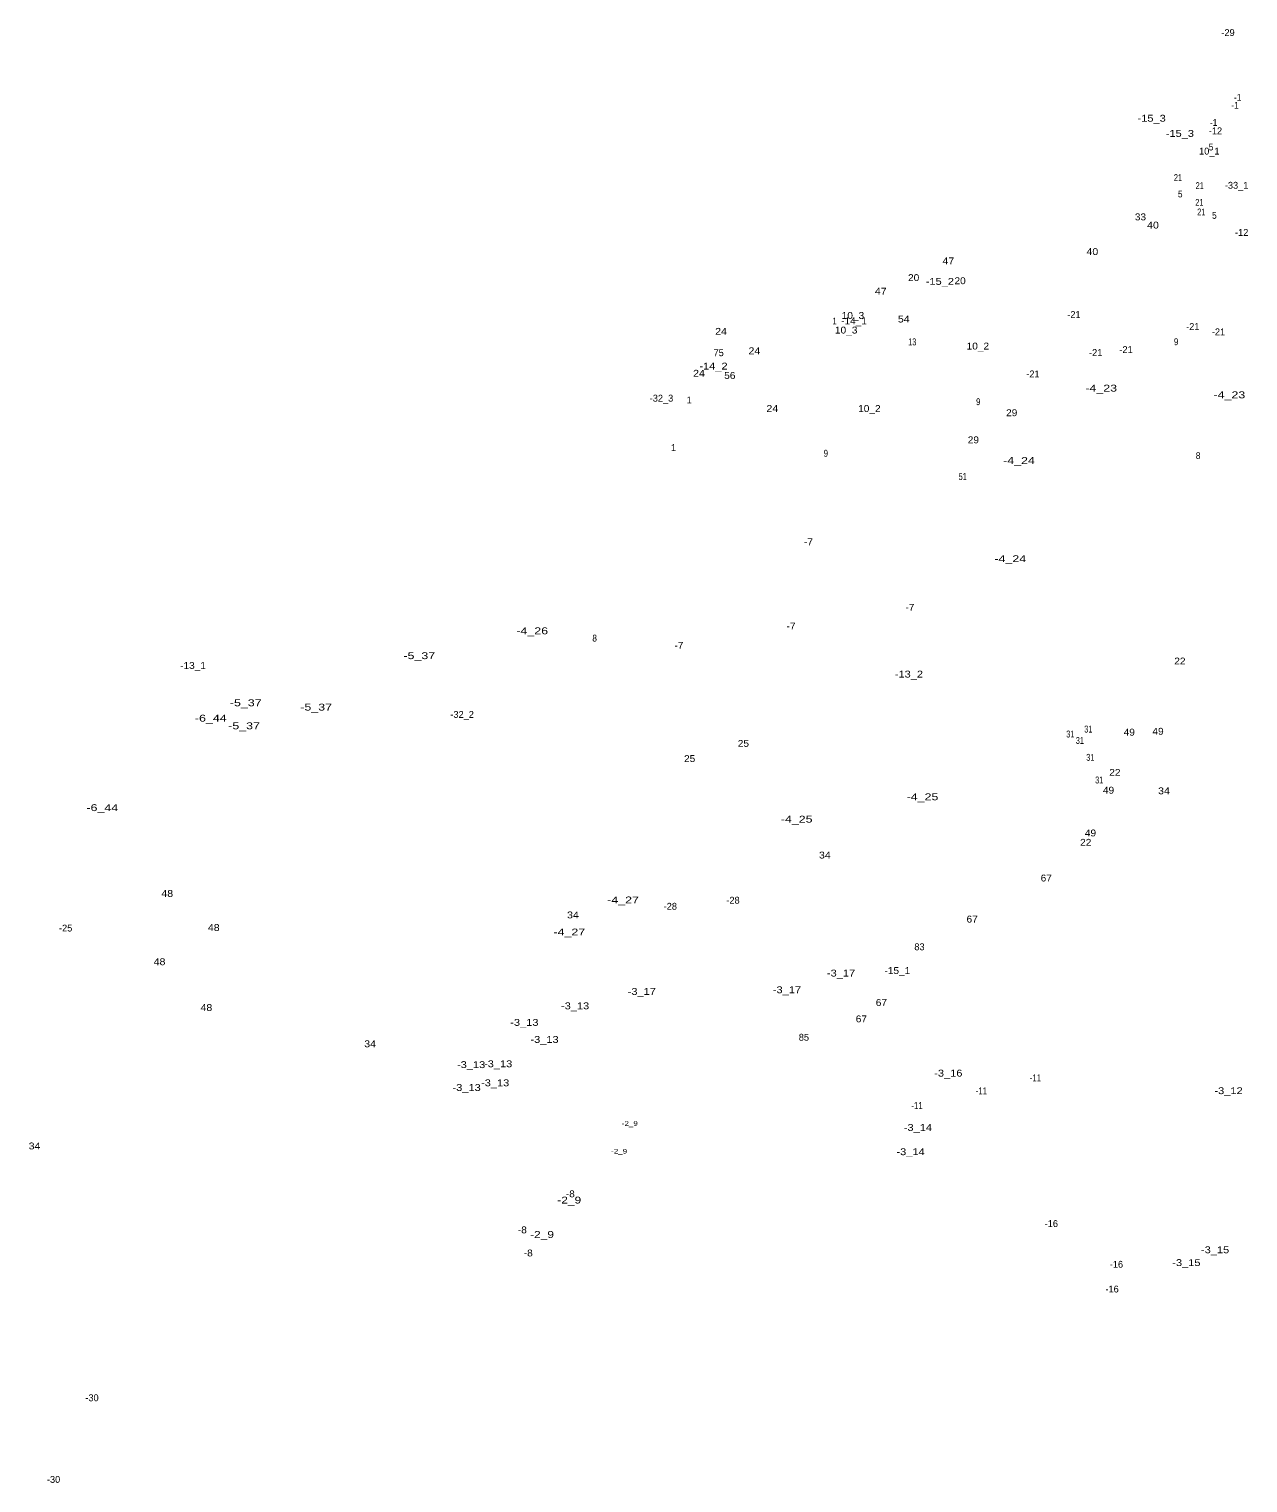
# Model space of a CAD drawing. Extents: x -660778 to -658007, y -986975 to -985382.
# Drawn here: x -659382 to -658674, y -986509 to -985663 of the extents above; entities that cross this region are included whole.
import ezdxf
from ezdxf.enums import TextEntityAlignment as Align

# ---------------------------------------------------------------- set-up
doc = ezdxf.new("R2010")
doc.units = 0
doc.header["$LTSCALE"] = 1.6
doc.layers.add('24', color=7, linetype='Continuous')

msp = doc.modelspace()

# ---------------------------------------------------------------- texts
at = {"layer": '24'}
for s, p in [('-29', (-658685.15, -985667.27)), ('-12', (-658692.441, -985724.41)), ('10_1', (-658696.03, -985736.19)), ('-33_1', (-658680.156, -985756.05)), ('-12', (-658677.201, -985783.44)), ('-21', (-658774.74, -985831.18)), ('-21', (-658705.64, -985838.17)), ('-21', (-658690.691, -985841.28)), ('-21', (-658744.461, -985851.57)), ('75', (-658981.363, -985853.42)), ('-21', (-658762.12, -985853.32)), ('-21', (-658798.611, -985865.75)), ('-32_3', (-659014.612, -985879.85)), ('1', (-658998.502, -985880.88)), ('1', (-659007.632, -985908.58)), ('-32_2', (-659130.542, -986063.75)), ('-28', (-658973.025, -986171.8)), ('-28', (-659009.475, -986175.32)), ('-25', (-659361.095, -986187.97)), ('83', (-658864.597, -986198.87)), ('85', (-658931.787, -986251.48)), ('-16', (-658787.9, -986359.83)), ('-16', (-658750.05, -986383.51)), ('-16', (-658752.57, -986397.88)), ('-30', (-659345.769, -986461.11)), ('-30', (-659368.119, -986508.57))]:
    msp.add_text(s, height=4, dxfattribs=at).set_placement(p, align=Align.CENTER)
for s, height, width, p in [('-1', 4, 0.9, (-658679.51, -985704.91)), ('-15_3', 4, 1.2, (-658729.549, -985717.07)), ('-1', 4, 0.9, (-658681.061, -985709.52)), ('-1', 4, 0.9, (-658693.53, -985719.52)), ('-15_3', 4, 1.2, (-658713.15, -985725.9)), ('5', 4, 0.9, (-658695, -985733.78)), ('21', 4, 0.8, (-658714.25, -985751.56)), ('21', 4, 0.8, (-658701.62, -985756.27)), ('5', 4, 0.9, (-658712.939, -985761.09)), ('21', 4, 0.8, (-658701.809, -985765.98)), ('33', 4, 1.1, (-658736.079, -985774.43)), ('21', 4, 0.8, (-658700.699, -985771.56)), ('5', 4, 0.9, (-658693.09, -985773.53)), ('40', 4, 1.15, (-658728.78, -985779.2)), ('47', 4, 1.15, (-658847.8, -985800.02)), ('40', 4, 1.15, (-658764.04, -985794.61)), ('20', 4, 1.1, (-658867.97, -985809.73)), ('47', 4, 1.15, (-658887.11, -985817.64)), ('-15_2', 4, 1.2, (-658852.73, -985811.93)), ('20', 4, 1.1, (-658840.959, -985811.56)), ('1', 4, 0.65, (-658913.927, -985834.98)), ('-14_1', 4, 1.1, (-658902.65, -985834.92)), ('10_3', 4, 1.1, (-658903.27, -985831.75)), ('54', 4, 1.15, (-658873.72, -985833.82)), ('24', 4, 1.15, (-658979.959, -985840.99)), ('10_3', 4, 1.1, (-658907.2, -985840.24)), ('24', 4, 1.15, (-658960.579, -985852.33)), ('13', 4, 0.8, (-658868.79, -985847.11)), ('10_2', 4, 1.1, (-658830.63, -985849.54)), ('9', 4, 0.85, (-658715.31, -985847.03)), ('24', 4, 1.15, (-658992.79, -985865.37)), ('-14_2', 4, 1.2, (-658984.36, -985861.17)), ('56', 4, 1.1, (-658974.86, -985866.64)), ('-4_23', 4, 1.35, (-658758.9, -985874.01)), ('-4_23', 4, 1.35, (-658684.36, -985877.89)), ('24', 4, 1.15, (-658950.169, -985885.85)), ('10_2', 4, 1.1, (-658893.71, -985885.85)), ('9', 4, 0.85, (-658830.4, -985881.88)), ('29', 4, 1.1, (-658810.94, -985888.31)), ('29', 4, 1.1, (-658833.24, -985904.08)), ('9', 4, 0.85, (-658919.02, -985911.88)), ('-4_24', 4, 1.35, (-658806.72, -985916.1)), ('8', 4, 0.9, (-658702.569, -985913.26)), ('51', 4, 0.8, (-658839.439, -985925.4)), ('-7', 4, 1.1, (-658929.15, -985963.39)), ('-4_24', 4, 1.35, (-658811.77, -985973.18)), ('-7', 4, 1.1, (-658870.15, -986001.45)), ('-7', 4, 1.1, (-658939.25, -986012.32)), ('-4_26', 4, 1.35, (-659089.78, -986015.13)), ('8', 4, 0.9, (-659053.48, -986019.37)), ('-5_37', 4, 1.35, (-659155.44, -986029.59)), ('-7', 4, 1.1, (-659004.471, -986023.58)), ('-13_1', 4, 1.1, (-659287.01, -986035.28)), ('22', 4, 1.1, (-658713.13, -986032.69)), ('-13_2', 4, 1.2, (-658870.73, -986040.3)), ('-5_37', 4, 1.35, (-659256.38, -986056.97)), ('-5_37', 4, 1.35, (-659215.42, -986059.5)), ('-6_44', 4, 1.35, (-659276.699, -986065.92)), ('-5_37', 4, 1.35, (-659257.35, -986070.37)), ('31', 4, 0.8, (-658766.4, -986072.26)), ('25', 4, 1.1, (-658966.98, -986080.58)), ('31', 4, 0.8, (-658776.87, -986075.14)), ('31', 4, 0.8, (-658771.299, -986078.89)), ('49', 4, 1.1, (-658742.58, -986074.08)), ('49', 4, 1.1, (-658725.85, -986073.55)), ('31', 4, 0.8, (-658765.24, -986088.7)), ('25', 4, 1.1, (-658998.22, -986089.42)), ('22', 4, 1.1, (-658750.949, -986097.44)), ('31', 4, 0.8, (-658760.049, -986101.87)), ('-4_25', 4, 1.35, (-658862.82, -986111.65)), ('49', 4, 1.1, (-658754.65, -986107.81)), ('34', 4, 1.15, (-658722.39, -986108.18)), ('-6_44', 4, 1.35, (-659339.78, -986117.96)), ('-4_25', 4, 1.35, (-658936, -986124.66)), ('22', 4, 1.1, (-658767.88, -986138.12)), ('49', 4, 1.1, (-658765.15, -986132.67)), ('34', 4, 1.15, (-658919.6, -986145.53)), ('67', 4, 1.1, (-658790.84, -986158.88)), ('48', 4, 1.15, (-659302.02, -986167.84)), ('-4_27', 4, 1.35, (-659036.939, -986171.63)), ('34', 4, 1.15, (-659066.1, -986180.35)), ('48', 4, 1.15, (-659274.98, -986187.7)), ('-4_27', 4, 1.35, (-659068.189, -986190.27)), ('67', 4, 1.1, (-658833.93, -986182.77)), ('48', 4, 1.15, (-659306.5, -986207.55)), ('-3_17', 4, 1.2, (-658910.19, -986214.16)), ('-15_1', 4, 1.1, (-658877.449, -986212.67)), ('-3_17', 4, 1.2, (-658941.64, -986223.86)), ('-3_17', 4, 1.2, (-659026.07, -986224.83)), ('67', 4, 1.1, (-658886.72, -986231.27)), ('48', 4, 1.15, (-659279.26, -986234.22)), ('-3_13', 4, 1.2, (-659064.84, -986233.21)), ('67', 4, 1.1, (-658898.37, -986240.79)), ('-3_13', 4, 1.2, (-659094.34, -986242.83)), ('34', 4, 1.15, (-659184.04, -986255.29)), ('-3_13', 4, 1.2, (-659082.6, -986252.73)), ('-3_13', 4, 1.2, (-659125.299, -986267.39)), ('-3_13', 4, 1.2, (-659109.579, -986266.9)), ('-3_16', 4, 1.2, (-658847.791, -986272.34)), ('-11', 4, 0.85, (-658797.13, -986275.06)), ('-3_13', 4, 1.2, (-659127.919, -986280.69)), ('-3_13', 4, 1.2, (-659111.319, -986277.97)), ('-11', 4, 0.85, (-658828.571, -986282.63)), ('-3_12', 4, 1.2, (-658684.84, -986282.55)), ('-11', 4, 0.85, (-658866.03, -986291.17)), ('-2_9', 2.68, 1.3, (-659033.02, -986300.99)), ('-3_14', 4, 1.2, (-658865.48, -986303.95)), ('34', 4, 1.15, (-659379.179, -986314.69)), ('-2_9', 2.68, 1.3, (-659039.23, -986317.1)), ('-3_14', 4, 1.2, (-658869.75, -986318.03)), ('-8', 4, 1.1, (-659067.62, -986342.52)), ('-2_9', 4, 1.3, (-659068.25, -986346.16)), ('-8', 4, 1.1, (-659095.52, -986363.49)), ('-2_9', 4, 1.3, (-659084.07, -986366.16)), ('-3_15', 4, 1.2, (-658692.679, -986375.06)), ('-8', 4, 1.1, (-659092.08, -986376.92)), ('-3_15', 4, 1.2, (-658709.37, -986382.53))]:
    msp.add_text(s, height=height, dxfattribs=dict(at, width=width)).set_placement(p, align=Align.CENTER)

doc.saveas('drawing.dxf')
